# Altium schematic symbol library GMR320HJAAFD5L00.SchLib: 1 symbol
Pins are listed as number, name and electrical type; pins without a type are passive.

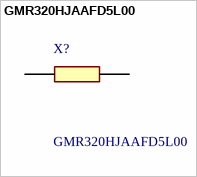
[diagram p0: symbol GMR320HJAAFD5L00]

## GMR320HJAAFD5L00
designator X?
7142 (2817) size, 10W, 5m, High Power Type Metal Plate Shunt Resistor (AEC-Q200 Qualified); Manufacturer_Name: ROHM Semiconductor; Geometry.Height: 0.55mm
footprint RESC7142X55N
pins: 1, 2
